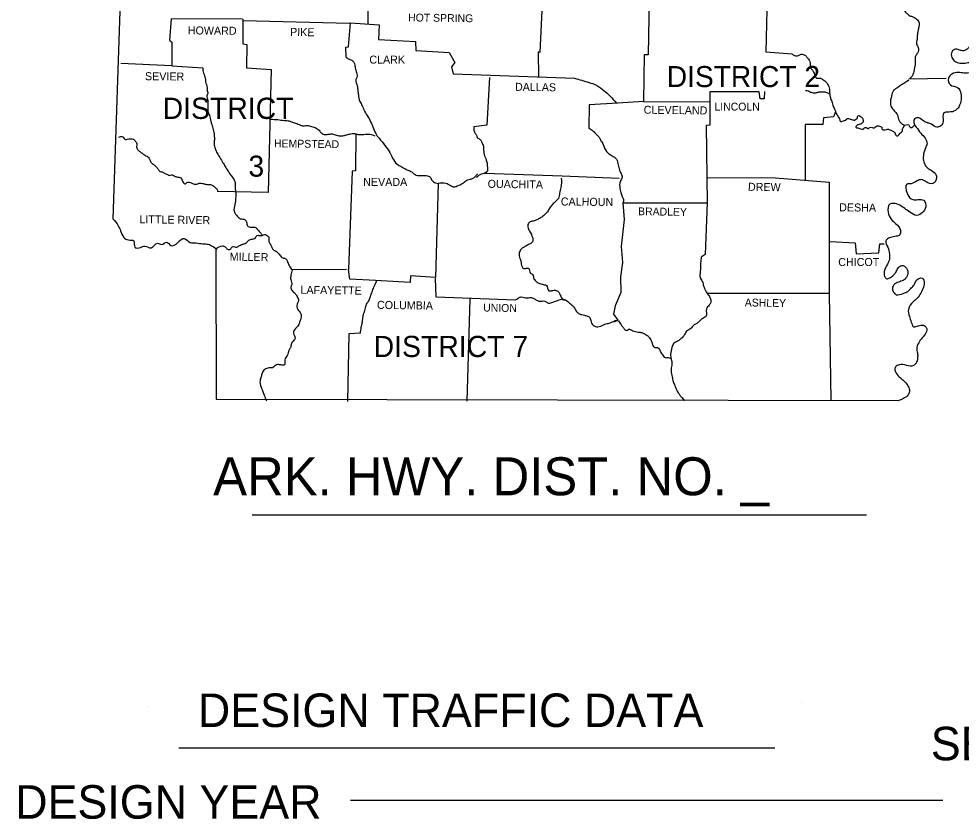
# Model space of a CAD drawing. Extents: x 23481 to 28196, y 1325020 to 1327623.
# Drawn here: x 26225 to 26731, y 1326499 to 1326929 of the extents above; entities that cross this region are included whole.
import ezdxf

# ---------------------------------------------------------------- set-up
doc = ezdxf.new("R2010")
doc.units = 0
doc.layers.add('S_ELECTRIC_UTILITIES_ANNOT', color=7, linetype='Continuous')

msp = doc.modelspace()

# ---------------------------------------------------------------- linework, layer by layer
at = {"layer": 'S_ELECTRIC_UTILITIES_ANNOT'}
for p, q in [((26413.1, 1326988.98), (26411.93, 1326926.18)), ((26702.6, 1326896.78), (26722.6, 1326897.08)), ((26349.8, 1326662.6), (26679.85, 1326662.6)), ((26294.12, 1326559.69), (26294.12, 1326559.69)), ((26644.92, 1326561.79), (26644.92, 1326561.79)), ((26310.52, 1326537.49), (26630.52, 1326537.49)), ((26402.61, 1326509.36), (26720.73, 1326509.36))]:
    msp.add_line(p, q, dxfattribs=at)
for points in [[(26263.4, 1327259.08), (26284.1, 1327092.88), (26275.1, 1326821.58)], [(26563.2, 1326950.28), (26562.6, 1326909.68), (26560.3, 1326909.58), (26560, 1326884.48)], [(26626.6, 1326948.98), (26625.8, 1326911.28), (26639.7, 1326910.18)], [(26505.6, 1326937.08), (26504.4, 1326910.88), (26503.5, 1326911.18), (26503.6, 1326897.58)], [(26344.7, 1326928.78), (26306.3, 1326928.88), (26305.4, 1326917.48), (26306.8, 1326916.48), (26306.7, 1326903.68), (26279.4, 1326904.88)], [(26344.8, 1326928.78), (26344.8, 1326915.48), (26347, 1326915.08), (26346.8, 1326902.68), (26360, 1326901.68), (26358.4, 1326835.58), (26331.2, 1326836.28)], [(26345, 1326928.08), (26402.2, 1326926.58)], [(26400.3, 1326908.28), (26400.1, 1326913.78), (26401.7, 1326913.88), (26402.7, 1326926.78), (26418.1, 1326925.78), (26417.7, 1326917.88), (26437.6, 1326916.78), (26437.7, 1326911.98), (26455.7, 1326910.88), (26458.8, 1326905.48), (26456.9, 1326903.08), (26457.8, 1326899.38), (26523, 1326896.98)], [(26306.7, 1326903.68), (26323.3, 1326902.68)], [(26477.4, 1326897.48), (26475.9, 1326871.78), (26469, 1326870.98)], [(26625.06, 1326889.94), (26624.9, 1326885.88), (26622.6, 1326885.88), (26622.2, 1326889.78), (26595.6, 1326889.78), (26595.63, 1326884.28)], [(26546.16, 1326883.62), (26530.8, 1326882.68), (26530.7, 1326870.18)], [(26560, 1326884.48), (26546.16, 1326883.62)], [(26560, 1326884.48), (26595.4, 1326884.28)], [(26595.63, 1326884.28), (26595.7, 1326871.78), (26593.6, 1326871.68), (26594.2, 1326830.18)], [(26663.2, 1326878.98), (26662, 1326876.28), (26656.7, 1326875.78), (26656.4, 1326872.18), (26646.9, 1326872.18), (26646.8, 1326842.28)], [(26700.2, 1326871.88), (26701.09, 1326871.95), (26701.76, 1326872.25), (26702.51, 1326872.01), (26702.73, 1326871.36), (26703.46, 1326870.66), (26704.3, 1326870.56), (26704.9, 1326871.05), (26705.55, 1326871.88)], [(26405.6, 1326867.18), (26405.4, 1326847.28), (26403.6, 1326847.08), (26401.6, 1326794.38)], [(26474.9, 1326846.08), (26516.3, 1326844.58), (26547, 1326843.38)], [(26593.9, 1326843.78), (26631, 1326843.48), (26659.8, 1326841.28)], [(26449.7, 1326840.48), (26448.4, 1326790.08), (26434.9, 1326790.98), (26434.8, 1326787.28), (26416.13, 1326788.37)], [(26659.8, 1326841.28), (26659.8, 1326781.48), (26660.6, 1326723.98)], [(26549, 1326830.08), (26549.56, 1326821.17), (26548.09, 1326806.69), (26548.72, 1326798.09), (26547.67, 1326790.33), (26547.88, 1326781.93), (26544.74, 1326774.8), (26543.9, 1326770.39), (26546.21, 1326767.03)], [(26549, 1326830.08), (26594.2, 1326830.18)], [(26594.2, 1326830.18), (26593.2, 1326802.38), (26591, 1326800.98)], [(26660.3, 1326809.38), (26673.7, 1326808.58), (26674.3, 1326802.78), (26686.4, 1326803.18), (26686.9, 1326808.08), (26689.2, 1326808.08)], [(26330.4, 1326805.48), (26330.6, 1326724.58), (26697.1, 1326723.98)], [(26400.48, 1326794.37), (26371.3, 1326794.08)], [(26416.13, 1326788.37), (26402.3, 1326789.18), (26401.6, 1326794.38)], [(26491.3, 1326777.88), (26448.6, 1326779.48), (26448.4, 1326789.58)], [(26466.8, 1326778.58), (26465.2, 1326723.68)], [(26594.8, 1326781.58), (26659.8, 1326781.58)], [(26408, 1326760.08), (26401.8, 1326759.68), (26401.1, 1326723.38)]]:
    msp.add_lwpolyline(points, dxfattribs=at)
for points in [[(26781.3, 1326994.08), (26779, 1326991.18), (26775.6, 1326992.98), (26775.6, 1326995.38), (26776.1, 1326997.88), (26774.9, 1326999.48), (26772.8, 1326998.78), (26772.8, 1326995.68), (26772.6, 1326992.68), (26772, 1326988.38), (26773.4, 1326987.08), (26776.6, 1326986.68), (26778.9, 1326986.08), (26780.3, 1326983.78), (26780.2, 1326980.98), (26779.1, 1326978.28), (26777.5, 1326976.08), (26775, 1326975.28), (26773, 1326976.58), (26772.2, 1326979.18), (26771.3, 1326981.48), (26769.6, 1326983.18), (26767.8, 1326981.28), (26767.4, 1326977.78), (26767.5, 1326974.78), (26767.5, 1326970.68), (26770.1, 1326967.98), (26771.7, 1326964.88), (26771.2, 1326962.08), (26769.3, 1326958.78), (26768.5, 1326955.88), (26767.7, 1326951.98), (26767.8, 1326947.68), (26767.1, 1326943.48), (26765.7, 1326940.68), (26763.1, 1326938.38), (26761.4, 1326936.88), (26760, 1326935.38), (26759.3, 1326932.38), (26758.8, 1326930.28), (26756.9, 1326927.78), (26755.4, 1326927.58), (26754.2, 1326928.58), (26753.8, 1326930.28), (26753.8, 1326931.98), (26753, 1326933.68), (26750.5, 1326934.38), (26748.5, 1326934.28), (26747.6, 1326932.88), (26748.9, 1326928.98), (26749.4, 1326926.48), (26748.7, 1326923.08), (26749.1, 1326922.68), (26745.5, 1326920.78), (26742.6, 1326920.48), (26740.2, 1326919.78), (26737.9, 1326918.28), (26736.8, 1326916.08), (26735.2, 1326914.28), (26733.8, 1326912.58), (26731.9, 1326911.78), (26729.8, 1326912.18), (26727, 1326912.48), (26725.4, 1326910.48), (26725.9, 1326907.58), (26727.8, 1326905.88), (26730.6, 1326905.08), (26733.5, 1326905.28), (26736.3, 1326905.58), (26738.9, 1326904.18), (26738.4, 1326901.48), (26735.9, 1326900.18), (26732.2, 1326899.78), (26729.2, 1326900.08), (26725.6, 1326899.28), (26723.8, 1326896.98), (26724.8, 1326893.48), (26728.7, 1326892.08), (26730.5, 1326888.78), (26730.6, 1326885.68), (26729.3, 1326881.58), (26727.5, 1326879.68), (26724, 1326878.88), (26721.3, 1326878.38), (26720.9, 1326873.78), (26719.7, 1326871.48), (26717.6, 1326870.78), (26714.6, 1326872.28), (26712.8, 1326872.98), (26710.6, 1326873.98), (26707.8, 1326875.68), (26705.7, 1326875.38), (26706.3, 1326870.98), (26706.5, 1326870.78), (26708.9, 1326867.48), (26711.3, 1326864.88), (26712.4, 1326861.78)], [(26677.7, 1326961.88), (26678, 1326957.78), (26680.4, 1326957.18), (26681.4, 1326956.08), (26681.9, 1326953.78), (26683.6, 1326952.78), (26685.9, 1326951.38), (26687.3, 1326950.38), (26688.3, 1326948.78), (26688.9, 1326946.18), (26690.5, 1326944.48), (26692.7, 1326943.68), (26694.3, 1326941.78), (26695.3, 1326939.08), (26696.9, 1326937.88), (26698.5, 1326935.78), (26699.3, 1326934.88), (26700.7, 1326932.48), (26702.1, 1326931.28), (26703.1, 1326930.58), (26704.7, 1326930.08), (26706.7, 1326928.78), (26708, 1326926.78), (26708, 1326925.28), (26707.5, 1326922.98), (26707.1, 1326920.58), (26706.9, 1326917.88), (26706.7, 1326915.48), (26707.6, 1326913.48), (26707.1, 1326910.48), (26706.1, 1326908.88), (26706, 1326906.68), (26705.7, 1326903.38), (26705.3, 1326901.48), (26704.4, 1326898.38), (26703.1, 1326896.78)], [(26639.7, 1326910.18), (26641.2, 1326909.18), (26643.3, 1326909.28), (26644.7, 1326909.88), (26645.8, 1326909.78), (26647.3, 1326908.88), (26648.3, 1326907.68), (26649, 1326906.78), (26649.5, 1326905.38), (26649.5, 1326904.08), (26650, 1326902.28), (26650.6, 1326901.58), (26651.4, 1326900.28), (26651.9, 1326899.08), (26652.2, 1326898.28), (26653.3, 1326896.98), (26654.3, 1326897.08), (26655.2, 1326896.98), (26656.4, 1326896.28), (26658.2, 1326894.88), (26658.5, 1326894.48), (26659.7, 1326891.88), (26659.9, 1326890.28), (26660.1, 1326888.18), (26660.5, 1326886.18), (26661.3, 1326883.98), (26661.7, 1326882.48), (26662.6, 1326880.38), (26663.2, 1326878.98), (26664, 1326877.18), (26665.2, 1326875.18), (26665.7, 1326873.98), (26667.4, 1326874.08), (26668.6, 1326874.58), (26669.5, 1326875.38), (26670.6, 1326875.28), (26671.8, 1326874.88), (26673.4, 1326874.58), (26674.4, 1326875.18), (26674.9, 1326875.58), (26675, 1326876.48), (26675.9, 1326876.98), (26676.9, 1326876.28), (26678, 1326874.68), (26678, 1326873.68), (26677.6, 1326873.08), (26676.3, 1326872.28), (26674.5, 1326871.68), (26674, 1326870.98), (26675.7, 1326870.18), (26678.4, 1326869.98), (26679.1, 1326870.58), (26680.9, 1326870.08), (26681.6, 1326870.58), (26684, 1326870.48), (26685.1, 1326871.28), (26687.3, 1326871.18), (26688, 1326870.68), (26688, 1326869.78), (26689.8, 1326869.38), (26691.1, 1326869.68), (26692.8, 1326869.18), (26694.3, 1326868.38), (26695.1, 1326867.28), (26696.1, 1326866.08), (26697, 1326866.38), (26697.7, 1326867.28), (26699.2, 1326868.88), (26699.2, 1326869.88), (26699.6, 1326870.58), (26700.1, 1326871.58)], [(26400.3, 1326908.28), (26401.9, 1326907.28), (26403.8, 1326906.38), (26404.8, 1326904.88), (26405.2, 1326902.58), (26405.9, 1326900.08), (26406.1, 1326897.48), (26405.5, 1326896.08), (26406.3, 1326892.88), (26406.6, 1326890.68), (26406.9, 1326888.08), (26407.7, 1326884.58), (26409, 1326882.18), (26410.2, 1326879.28), (26412.2, 1326876.18), (26413.9, 1326872.78), (26414.7, 1326870.98), (26416.2, 1326867.28), (26418.1, 1326864.78), (26421.1, 1326860.98), (26423.8, 1326857.08), (26425.3, 1326854.18), (26427.6, 1326850.98), (26430.2, 1326849.38), (26433.5, 1326847.68), (26435.6, 1326846.68), (26438, 1326844.98), (26441.1, 1326844.78), (26443.4, 1326844.78), (26445.5, 1326843.88), (26446.5, 1326842.08), (26448.3, 1326840.88), (26449.7, 1326840.48)], [(26323.3, 1326902.68), (26323.8, 1326899.68), (26324.7, 1326897.08), (26324.8, 1326895.08), (26325.7, 1326892.08), (26325.7, 1326890.98), (26326, 1326888.78), (26325.6, 1326887.58), (26326.1, 1326885.18), (26326, 1326883.38), (26326, 1326881.88), (26326.1, 1326879.38), (26326.9, 1326877.18), (26327.7, 1326873.88), (26328.2, 1326872.18), (26329, 1326869.58), (26329.5, 1326866.38), (26329.6, 1326863.98), (26329.4, 1326861.78), (26330, 1326859.28), (26331.1, 1326856.78), (26332.5, 1326854.38), (26334.2, 1326851.68), (26335.4, 1326849.58), (26336.9, 1326847.28), (26338.1, 1326845.38), (26339.9, 1326842.98), (26340.7, 1326840.98), (26340.7, 1326838.18), (26341.1, 1326835.58), (26341, 1326832.68), (26340.8, 1326830.08), (26340.1, 1326826.48), (26340.6, 1326824.78), (26342.5, 1326822.28), (26343.7, 1326821.58), (26345.8, 1326821.18), (26346.8, 1326819.78), (26347.4, 1326817.68), (26349.5, 1326816.98), (26351.8, 1326816.78), (26352.9, 1326815.58), (26354.4, 1326813.98), (26354.9, 1326813.18)], [(26523, 1326896.98), (26530.8, 1326894.78), (26534.8, 1326893.28), (26538.8, 1326890.38), (26542.1, 1326887.48), (26545.4, 1326883.78)], [(26702.4, 1326896.18), (26700.3, 1326894.48), (26698.5, 1326893.48), (26696.6, 1326892.08), (26694.3, 1326890.38), (26693.2, 1326887.48), (26692.6, 1326883.48), (26693.4, 1326881.08), (26695.2, 1326878.98), (26696.4, 1326877.28), (26697.3, 1326874.28), (26699.5, 1326872.18), (26700.2, 1326871.88)], [(26647.1, 1326890.49), (26647.3, 1326890.48), (26648.6, 1326890.18), (26649.7, 1326889.58), (26650.5, 1326889.38), (26651.7, 1326889.18), (26652.7, 1326889.28), (26654.4, 1326889.68), (26655.4, 1326889.68), (26657, 1326889.68), (26658, 1326889.58), (26659.5, 1326888.78)], [(26359.8, 1326875.08), (26363.6, 1326874.78), (26367.1, 1326874.38), (26369.8, 1326874.08), (26372.6, 1326873.08), (26375.1, 1326872.18), (26376.7, 1326871.48), (26379.4, 1326871.68), (26381.7, 1326871.18), (26384.3, 1326870.28), (26386.2, 1326868.58), (26387.4, 1326867.28), (26389.7, 1326866.78), (26391.6, 1326867.08), (26393.9, 1326866.88), (26396.5, 1326866.08), (26398.6, 1326866.18), (26400.3, 1326866.58), (26402.3, 1326867.08), (26404.8, 1326867.28), (26406.7, 1326866.88), (26409.2, 1326866.78), (26412.1, 1326867.08), (26415.7, 1326866.08)], [(26469, 1326870.98), (26469, 1326869.08), (26469.7, 1326867.28), (26470.4, 1326866.48), (26470.7, 1326865.18), (26471.6, 1326864.58), (26472.9, 1326863.38), (26473.6, 1326861.68), (26474.1, 1326860.58), (26474.1, 1326859.18), (26474.2, 1326857.78), (26474.4, 1326856.08), (26475.6, 1326853.08), (26475.9, 1326851.88), (26476.1, 1326850.88), (26476.2, 1326849.18), (26476.2, 1326847.18), (26474.9, 1326846.08)], [(26530.7, 1326870.18), (26533, 1326868.68), (26534.9, 1326866.68), (26536.3, 1326865.18), (26537.2, 1326863.48), (26538.4, 1326861.48), (26540.1, 1326857.68), (26541.6, 1326856.38), (26543.7, 1326855.08), (26545, 1326854.18), (26546.3, 1326851.28), (26546.9, 1326848.38), (26548, 1326845.78), (26548.5, 1326843.78), (26547.6, 1326841.78), (26547.4, 1326837.78), (26548, 1326835.08), (26548.8, 1326833.08), (26549.3, 1326830.78), (26549, 1326830.08)], [(26278.2, 1326865.38), (26280.4, 1326865.48), (26281.9, 1326864.18), (26282.8, 1326864.28), (26284.4, 1326864.48), (26285.9, 1326864.38), (26287, 1326863.48), (26287.9, 1326861.88), (26287.8, 1326860.38), (26287.9, 1326859.78), (26288.6, 1326858.48), (26289.8, 1326857.48), (26291.1, 1326856.48), (26292.3, 1326855.68), (26294.3, 1326854.38), (26294.5, 1326853.98), (26295.3, 1326852.38), (26296.3, 1326851.08), (26297.5, 1326850.28), (26298.8, 1326848.88), (26299.4, 1326848.28), (26300.4, 1326846.88), (26301.5, 1326846.78), (26303, 1326845.88), (26304.1, 1326845.58), (26305.3, 1326844.78), (26306.5, 1326845.18), (26308, 1326844.58), (26310, 1326843.98), (26311.1, 1326843.78), (26312.4, 1326841.88), (26313.7, 1326840.28), (26315.3, 1326841.18), (26318.3, 1326840.28), (26320.2, 1326840.18), (26321.9, 1326840.68), (26323.2, 1326840.58), (26325.6, 1326839.98), (26327.1, 1326839.98), (26328.7, 1326839.38), (26330.2, 1326838.18), (26331.2, 1326836.88), (26331.2, 1326836.28)], [(26712.4, 1326861.78), (26711.4, 1326859.48), (26710.3, 1326855.48), (26710.6, 1326852.08), (26712.1, 1326849.18), (26714.5, 1326847.58), (26717.1, 1326845.28), (26716.9, 1326841.78), (26715.4, 1326840.48), (26711.9, 1326841.38), (26709.2, 1326842.58), (26706.9, 1326841.88), (26703.8, 1326840.38), (26701.5, 1326840.08), (26701.6, 1326835.28), (26704.7, 1326831.88), (26707.4, 1326831.88), (26710.5, 1326831.48), (26711.6, 1326827.88), (26709.8, 1326824.88), (26706.8, 1326823.38), (26703, 1326825.18), (26700.3, 1326827.08), (26697.6, 1326828.88), (26694.2, 1326829.78), (26692.3, 1326829.38), (26691.4, 1326825.18), (26693, 1326821.38), (26695.6, 1326818.78), (26698, 1326815.38), (26697.6, 1326812.88), (26695.8, 1326812.18), (26692.6, 1326811.48), (26690.7, 1326810.48), (26690.2, 1326809.68), (26691.2, 1326806.28), (26692.1, 1326802.58), (26692.1, 1326799.78), (26691, 1326797.18), (26689.3, 1326793.18), (26689.5, 1326790.58), (26690.7, 1326789.38), (26692.2, 1326789.78), (26694.2, 1326791.18), (26695.5, 1326792.78), (26696.6, 1326794.78), (26698.7, 1326796.48), (26701.3, 1326794.98), (26701.9, 1326791.88), (26700.4, 1326789.18), (26698.3, 1326787.98), (26695.7, 1326786.98), (26693.8, 1326784.78), (26694.3, 1326782.18), (26695.8, 1326780.78), (26699.5, 1326781.48), (26702, 1326782.58), (26703.4, 1326783.98), (26705.1, 1326785.68), (26706, 1326787.38), (26707.3, 1326789.18), (26709.6, 1326789.68), (26710.7, 1326788.18), (26710.3, 1326784.78), (26708.9, 1326781.58), (26707, 1326778.88), (26704.9, 1326776.98), (26702.3, 1326772.88), (26702.8, 1326769.08), (26703.8, 1326765.98), (26705.2, 1326763.58), (26707.6, 1326764.08), (26710.3, 1326764.38), (26711.9, 1326763.08), (26711.7, 1326760.28), (26709.7, 1326757.58), (26707.8, 1326754.98), (26706.8, 1326751.38), (26707.2, 1326748.88), (26707.2, 1326746.58), (26706.4, 1326744.08), (26705, 1326742.68), (26701.3, 1326742.78), (26697.4, 1326743.18), (26695.3, 1326741.98), (26695.7, 1326738.58), (26698, 1326736.08), (26699.6, 1326734.78), (26701.9, 1326731.98), (26702.9, 1326729.68), (26702.6, 1326727.68), (26701.2, 1326725.98), (26697.1, 1326723.98)], [(26470.8, 1326845.58), (26469.7, 1326844.28), (26468.4, 1326843.18), (26466.9, 1326842.68), (26465.5, 1326842.28), (26463.7, 1326841.08), (26462.3, 1326840.08), (26460.4, 1326839.18), (26458.6, 1326838.58), (26456.4, 1326839.28), (26455.2, 1326839.98), (26453.9, 1326840.48), (26449.7, 1326840.48)], [(26470.4, 1326843.98), (26473, 1326845.68), (26475.9, 1326846.08)], [(26515.9, 1326843.38), (26515.7, 1326838.38), (26515, 1326835.28), (26514.3, 1326832.48), (26512.8, 1326830.88), (26511.2, 1326829.28), (26509.7, 1326827.48), (26508.4, 1326825.28), (26507.1, 1326823.88), (26505.4, 1326822.48), (26503.7, 1326821.48), (26501.8, 1326820.58), (26499.7, 1326820.08), (26498.2, 1326818.98), (26498.1, 1326816.58), (26499.8, 1326813.18), (26500.4, 1326811.58), (26500.6, 1326809.68), (26499.9, 1326808.58), (26498.3, 1326807.68), (26496.4, 1326806.58), (26494.7, 1326805.58), (26493.5, 1326803.88), (26493.3, 1326801.58), (26494.1, 1326798.88), (26494.4, 1326797.28), (26495.7, 1326794.78), (26496.7, 1326794.88), (26498.5, 1326794.78), (26498.7, 1326794.28), (26498.8, 1326793.78), (26499.2, 1326792.48), (26500.7, 1326791.38), (26500.9, 1326790.38), (26501.8, 1326788.48), (26503.3, 1326787.18), (26504.4, 1326786.78), (26506.7, 1326786.08), (26507.9, 1326785.78), (26509.2, 1326782.88), (26510.8, 1326782.98), (26512, 1326783.18), (26514, 1326782.68), (26514.9, 1326781.48), (26515.8, 1326779.48), (26517, 1326778.08), (26517.8, 1326778.08)], [(26275.1, 1326821.58), (26278, 1326817.78), (26279.2, 1326815.08), (26280.9, 1326811.58), (26283.4, 1326810.18), (26286.3, 1326809.68), (26286.9, 1326806.28), (26289.9, 1326806.18), (26292.3, 1326806.88), (26295.6, 1326805.98), (26299.1, 1326808.38), (26301.1, 1326807.78), (26304, 1326808.98), (26306.2, 1326807.18), (26310, 1326808.78), (26313.4, 1326810.98), (26316.6, 1326808.88), (26319.7, 1326808.58), (26323.4, 1326808.08), (26326.3, 1326807.88), (26328.9, 1326806.58), (26330.8, 1326805.28), (26330.4, 1326805.48)], [(26330.4, 1326805.48), (26333.9, 1326806.98), (26335.4, 1326806.48), (26336.7, 1326805.18), (26338.2, 1326805.18), (26339, 1326806.38), (26340.5, 1326806.48), (26341.7, 1326806.38), (26343, 1326807.18), (26344.1, 1326807.68), (26345.6, 1326808.18), (26346.7, 1326808.58), (26347.7, 1326809.68), (26349.5, 1326810.58), (26351.6, 1326811.28), (26352.2, 1326812.28), (26353.2, 1326812.68), (26355.2, 1326812.58), (26356.5, 1326813.18), (26357.6, 1326812.68), (26358.6, 1326811.98), (26358.8, 1326809.38), (26359.6, 1326807.98), (26360.8, 1326805.48), (26362.5, 1326804.18), (26364.1, 1326802.88), (26364.7, 1326802.08), (26366.4, 1326800.58), (26367.9, 1326800.08), (26368.6, 1326798.98), (26369.7, 1326796.38), (26371.3, 1326794.08)], [(26591, 1326800.98), (26590.7, 1326797.88), (26590.6, 1326794.98), (26590.4, 1326792.18), (26590.4, 1326790.08), (26591.6, 1326787.78), (26592.3, 1326785.58), (26593, 1326783.68), (26594.4, 1326781.18), (26595.7, 1326779.28), (26596.1, 1326776.58), (26595.3, 1326775.18), (26593.8, 1326773.08), (26593.7, 1326769.28), (26591.9, 1326768.08), (26589.6, 1326766.08), (26588.3, 1326765.18), (26586.9, 1326764.28), (26585.4, 1326762.68), (26583.2, 1326761.18), (26581.6, 1326758.68), (26579.8, 1326756.78), (26578.3, 1326755.78), (26576.2, 1326754.48), (26575.3, 1326752.48), (26574.6, 1326748.78), (26574.9, 1326746.08), (26575.3, 1326743.68), (26574.8, 1326740.68), (26575.3, 1326737.38), (26575.8, 1326734.78), (26576.6, 1326732.48), (26577.7, 1326729.88), (26579.1, 1326727.48), (26582.1, 1326723.78)], [(26371.3, 1326794.08), (26370.7, 1326791.18), (26370.6, 1326788.88), (26371.1, 1326786.18), (26370.6, 1326784.88), (26371.4, 1326782.98), (26372.9, 1326781.48), (26374, 1326779.88), (26374.7, 1326777.58), (26373.8, 1326774.98), (26374.8, 1326772.28), (26375.7, 1326771.28), (26376.2, 1326769.68), (26375.5, 1326766.58), (26374.6, 1326764.28), (26372.6, 1326761.98), (26372, 1326760.88), (26372.3, 1326759.38), (26372.8, 1326756.98), (26372.3, 1326756.28), (26371, 1326754.58), (26370.6, 1326752.68), (26369.7, 1326751.08), (26368.7, 1326748.18), (26367.4, 1326745.78), (26367.2, 1326743.08), (26365.2, 1326743.08), (26362.9, 1326743.08), (26360.8, 1326741.58), (26358.9, 1326741.48), (26356.6, 1326740.58), (26355.2, 1326738.68), (26354.7, 1326736.58), (26354.1, 1326734.58), (26354.7, 1326731.18), (26355.6, 1326728.78), (26356.3, 1326726.88), (26357.5, 1326723.78)], [(26408, 1326760.08), (26408.5, 1326763.28), (26409, 1326765.78), (26409.3, 1326768.18), (26409.9, 1326770.88), (26410.8, 1326773.78), (26411.6, 1326776.18), (26412.7, 1326777.88), (26413.4, 1326779.88), (26414.3, 1326782.28), (26415.2, 1326784.78), (26416.8, 1326787.98)], [(26491.3, 1326777.88), (26492.9, 1326778.98), (26494.4, 1326779.58), (26495.9, 1326779.28), (26497.5, 1326779.08), (26498.9, 1326779.28), (26500.7, 1326778.98), (26502.2, 1326778.08), (26503.9, 1326777.38), (26505.6, 1326777.38), (26507.1, 1326777.38), (26508.4, 1326776.48), (26510.8, 1326776.58), (26512.8, 1326777.38), (26514.8, 1326777.98), (26517.5, 1326778.28), (26519.9, 1326776.58), (26521.6, 1326775.18), (26523, 1326773.58), (26524, 1326771.78), (26525.1, 1326770.78), (26526.9, 1326770.08), (26528.3, 1326769.78), (26530, 1326769.28), (26530.9, 1326768.88), (26531.7, 1326766.98), (26533, 1326764.38), (26535.5, 1326763.48), (26538.6, 1326764.68), (26541.1, 1326765.38), (26542.9, 1326765.98), (26544, 1326766.38), (26545, 1326766.48), (26544.7, 1326766.68), (26545.9, 1326766.98), (26547, 1326766.18), (26547.7, 1326765.08), (26548.9, 1326763.48), (26550, 1326762.08), (26551.1, 1326761.58), (26552.2, 1326762.18), (26553.7, 1326761.68), (26555, 1326761.18), (26556.5, 1326760.78), (26557.8, 1326760.68), (26559.5, 1326760.28), (26560.8, 1326759.58), (26562, 1326758.88), (26563.2, 1326757.58), (26564.4, 1326755.58), (26564.8, 1326753.98), (26566.2, 1326752.38), (26567.5, 1326752.38), (26569.4, 1326749.78), (26570.1, 1326748.78), (26571.6, 1326746.98), (26572.7, 1326746.98), (26574.8, 1326746.58)]]:
    msp.add_spline(points, degree=3, dxfattribs=at)

# ---------------------------------------------------------------- texts
for s, height, rotation, p in [('HOT SPRING', 4.201, 359.2216, (26433.6, 1326927.58)), ('HOWARD', 4.301, 359.5145, (26315.3, 1326920.58)), ('PIKE', 4.299, 359.0452, (26370.2, 1326919.78)), ('SEVIER', 4.301, 359.4271, (26292.3, 1326895.98)), ('DALLAS', 4.3, 359.2462, (26491, 1326890.28)), ('CLEVELAND', 4.301, 359.3376, (26560.1, 1326877.98)), ('HEMPSTEAD', 4.199, 359.1885, (26361.6, 1326859.98)), ('OUACHITA', 4.301, 359.2043, (26476.3, 1326838.18)), ('DREW', 4.299, 359.2258, (26616.1, 1326836.58)), ('CALHOUN', 4.301, 359.3634, (26515.6, 1326828.68)), ('BRADLEY', 4.199, 359.1449, (26557.1, 1326823.48)), ('DESHA', 4.299, 359.3704, (26665.1, 1326825.58)), ('LITTLE RIVER', 4.3007, 359.1697, (26289.3, 1326819.18)), ('MILLER', 4.3, 359.1319, (26337.8, 1326799.08)), ('LAFAYETTE', 4.299, 359.1839, (26375.8, 1326781.28)), ('COLUMBIA', 4.3, 359.2125, (26416.9, 1326773.18)), ('ASHLEY', 4.201, 359.2361, (26614.4, 1326774.48)), ('UNION', 4.201, 358.9584, (26473.9, 1326771.78))]:
    msp.add_text(s, height=height, rotation=rotation, dxfattribs=at).set_placement(p)
for s, height, p in [('CLARK', 4.3, (26412.8, 1326904.88)), ('DISTRICT 2', 11.3, (26572.54, 1326892.27)), ('DISTRICT', 11.4, (26301.8, 1326875.18)), ('LINCOLN', 4.2, (26598.1, 1326879.68)), ('3', 11.3, (26347.9, 1326844.18)), ('NEVADA', 4.3, (26409.5, 1326839.18)), ('CHICOT', 4.3, (26664.6, 1326796.18)), ('DISTRICT 7', 11.4, (26415.1, 1326747.28)), ('  ARK. HWY. DIST. NO. _', 20.4, (26313.76, 1326673.05)), ('DESIGN TRAFFIC DATA', 18, (26320.72, 1326548.59)), ('SECTION', 18, (26714.3, 1326530.72)), ('DESIGN YEAR', 18, (26222.61, 1326499.36))]:
    msp.add_text(s, height=height, dxfattribs=at).set_placement(p)

doc.saveas('drawing.dxf')
